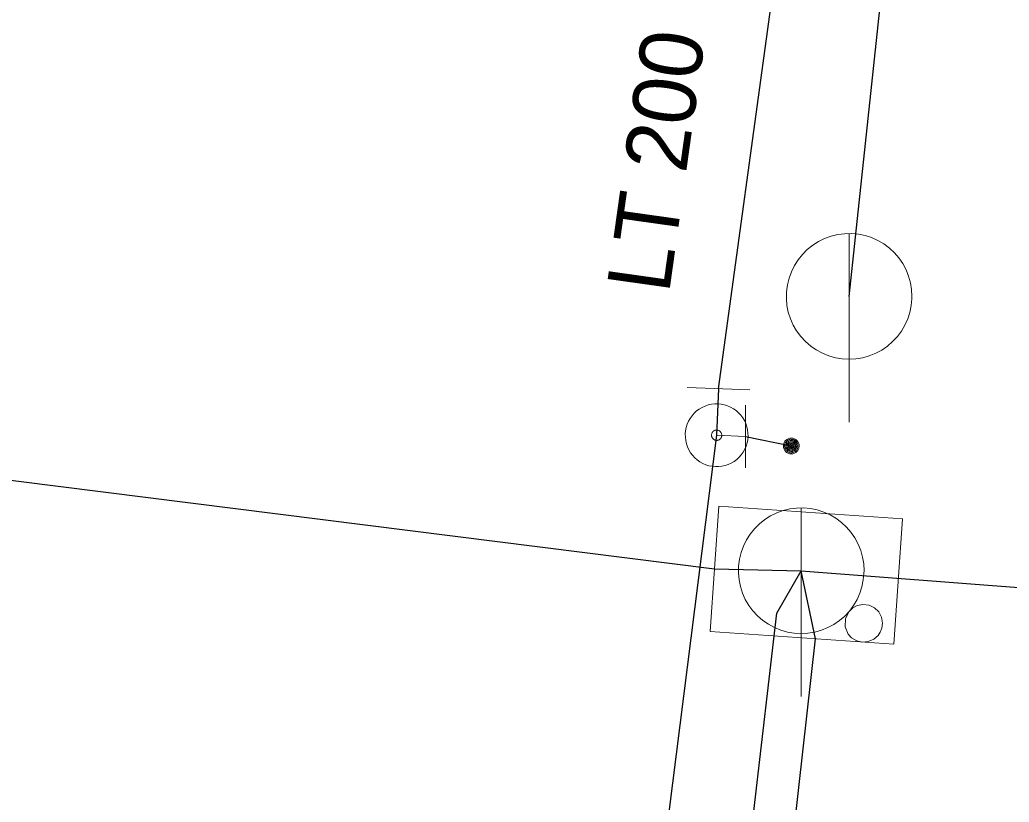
# Model space of a CAD drawing. Extents: x -783064 to -782702, y -1007904 to -1007145.
# Drawn here: x -782795.29 to -782779.54, y -1007420.35 to -1007407.9 of the extents above; entities that cross this region are included whole.
import ezdxf

# ---------------------------------------------------------------- set-up
doc = ezdxf.new("R2010")
doc.units = 0
doc.header["$LTSCALE"] = 0.4
for name, color, linetype, lineweight in [('1', 7, 'Continuous', 13), ('14', 7, 'Continuous', 13), ('17', 7, 'Continuous', 25), ('22', 7, 'Continuous', 13), ('34', 7, 'Continuous', 13), ('47', 7, 'Continuous', 13), ('9', 7, 'Continuous', 13)]:
    doc.layers.add(name, color=color, linetype=linetype, lineweight=lineweight)

msp = doc.modelspace()

# ---------------------------------------------------------------- linework, layer by layer
at = {"layer": '1'}
for points in [[(-782784.165, -1007415.638), (-782781.242, -1007415.839), (-782781.38, -1007417.835), (-782784.303, -1007417.633)], [(-782782.105, -1007417.672), (-782782.153, -1007417.558), (-782782.149, -1007417.428), (-782782.097, -1007417.32), (-782782.032, -1007417.256), (-782781.962, -1007417.219), (-782781.87, -1007417.201), (-782781.773, -1007417.213), (-782781.686, -1007417.255), (-782781.619, -1007417.32), (-782781.574, -1007417.403), (-782781.558, -1007417.501), (-782781.569, -1007417.581), (-782781.594, -1007417.643), (-782781.628, -1007417.694), (-782781.698, -1007417.755), (-782781.788, -1007417.793), (-782781.878, -1007417.8), (-782781.969, -1007417.78), (-782782.05, -1007417.732)]]:
    msp.add_lwpolyline(points, close=True, dxfattribs=at)
at = {"layer": '14'}
msp.add_line((-782784.199, -1007414.51), (-782783.739, -1007414.53), dxfattribs=at)
at = {"layer": '14', "lineweight": 25}
msp.add_line((-782782.853, -1007416.665), (-782749.03, -1007419.27), dxfattribs=at)
for points in [[(-782782.09, -1007412.3), (-782779.714, -1007390.038), (-782779.371, -1007386.822), (-782778.267, -1007376.47), (-782778.092, -1007374.836), (-782777.771, -1007371.826), (-782777.162, -1007366.117), (-782777.052, -1007365.088), (-782776.611, -1007360.948), (-782776.357, -1007358.573), (-782775.227, -1007347.977), (-782775.18, -1007347.535), (-782774.984, -1007345.702), (-782774.133, -1007337.723)], [(-782816.93, -1007412.519), (-782784.234, -1007416.636), (-782782.853, -1007416.665)], [(-782789.989, -1007474.3), (-782789.55, -1007470.605), (-782788.26, -1007459.742), (-782786.499, -1007444.926), (-782784.094, -1007424.689), (-782783.243, -1007417.342), (-782782.853, -1007416.665)], [(-782789.92, -1007482.8), (-782782.627, -1007417.749), (-782782.853, -1007416.665)]]:
    msp.add_lwpolyline(points, dxfattribs=at)
at = {"layer": '17'}
for p, q in [((-782784.17, -1007413.77), (-782782.979, -1007405.1)), ((-782784.17, -1007413.77), (-782784.199, -1007414.51)), ((-782783.739, -1007414.53), (-782783.01, -1007414.68))]:
    msp.add_line(p, q, dxfattribs=at)
msp.add_lwpolyline([(-782784.199, -1007414.51), (-782788.17, -1007445.88), (-782789.899, -1007459.31), (-782791.09, -1007469.35), (-782793.219, -1007488.27), (-782794.285, -1007499.072), (-782794.78, -1007504.08), (-782795.89, -1007514.14), (-782797.23, -1007526.05), (-782799.52, -1007547.12), (-782801.219, -1007562.54)], dxfattribs=at)
at = {"layer": '22'}
for p, q in [((-782782.09, -1007414.3), (-782782.089, -1007411.3)), ((-782782.853, -1007418.665), (-782782.852, -1007415.665))]:
    msp.add_line(p, q, dxfattribs=at)
for points in [[(-782781.09, -1007412.3), (-782781.095, -1007412.191), (-782781.113, -1007412.083), (-782781.143, -1007411.977), (-782781.183, -1007411.876), (-782781.235, -1007411.779), (-782781.297, -1007411.689), (-782781.369, -1007411.606), (-782781.449, -1007411.532), (-782781.537, -1007411.466), (-782781.631, -1007411.411), (-782781.731, -1007411.366), (-782781.836, -1007411.333), (-782781.943, -1007411.311), (-782782.052, -1007411.301), (-782782.162, -1007411.303), (-782782.27, -1007411.317), (-782782.377, -1007411.342), (-782782.48, -1007411.379), (-782782.578, -1007411.428), (-782782.67, -1007411.486), (-782782.756, -1007411.555), (-782782.833, -1007411.632), (-782782.902, -1007411.718), (-782782.961, -1007411.81), (-782783.009, -1007411.908), (-782783.046, -1007412.011), (-782783.072, -1007412.118), (-782783.086, -1007412.226), (-782783.089, -1007412.336), (-782783.079, -1007412.445), (-782783.058, -1007412.552), (-782783.024, -1007412.656), (-782782.98, -1007412.756), (-782782.925, -1007412.851), (-782782.859, -1007412.939), (-782782.785, -1007413.019), (-782782.702, -1007413.091), (-782782.612, -1007413.153), (-782782.516, -1007413.205), (-782782.414, -1007413.246), (-782782.309, -1007413.276), (-782782.201, -1007413.294), (-782782.091, -1007413.3), (-782781.982, -1007413.294), (-782781.874, -1007413.276), (-782781.769, -1007413.247), (-782781.667, -1007413.206), (-782781.57, -1007413.154), (-782781.48, -1007413.092), (-782781.397, -1007413.021), (-782781.322, -1007412.941), (-782781.257, -1007412.853), (-782781.201, -1007412.759), (-782781.157, -1007412.659), (-782781.123, -1007412.555), (-782781.101, -1007412.447), (-782781.091, -1007412.338)], [(-782781.853, -1007416.665), (-782781.858, -1007416.556), (-782781.876, -1007416.448), (-782781.906, -1007416.342), (-782781.946, -1007416.241), (-782781.998, -1007416.144), (-782782.06, -1007416.054), (-782782.132, -1007415.971), (-782782.212, -1007415.897), (-782782.3, -1007415.831), (-782782.394, -1007415.776), (-782782.494, -1007415.731), (-782782.599, -1007415.698), (-782782.706, -1007415.676), (-782782.815, -1007415.666), (-782782.925, -1007415.668), (-782783.033, -1007415.682), (-782783.14, -1007415.707), (-782783.243, -1007415.744), (-782783.341, -1007415.793), (-782783.433, -1007415.851), (-782783.519, -1007415.92), (-782783.596, -1007415.997), (-782783.665, -1007416.083), (-782783.724, -1007416.175), (-782783.772, -1007416.273), (-782783.809, -1007416.376), (-782783.835, -1007416.483), (-782783.849, -1007416.591), (-782783.852, -1007416.701), (-782783.842, -1007416.81), (-782783.821, -1007416.917), (-782783.787, -1007417.021), (-782783.743, -1007417.121), (-782783.688, -1007417.216), (-782783.622, -1007417.304), (-782783.548, -1007417.384), (-782783.465, -1007417.456), (-782783.375, -1007417.518), (-782783.279, -1007417.57), (-782783.177, -1007417.611), (-782783.072, -1007417.641), (-782782.964, -1007417.659), (-782782.854, -1007417.665), (-782782.745, -1007417.659), (-782782.637, -1007417.641), (-782782.532, -1007417.612), (-782782.43, -1007417.571), (-782782.333, -1007417.519), (-782782.243, -1007417.457), (-782782.16, -1007417.386), (-782782.085, -1007417.306), (-782782.02, -1007417.218), (-782781.964, -1007417.124), (-782781.92, -1007417.024), (-782781.886, -1007416.92), (-782781.864, -1007416.812), (-782781.854, -1007416.703)]]:
    msp.add_lwpolyline(points, close=True, dxfattribs=at)
at = {"layer": '34'}
for p, q in [((-782783.67, -1007413.789), (-782784.669, -1007413.749)), ((-782783.739, -1007414.03), (-782783.739, -1007415.03))]:
    msp.add_line(p, q, dxfattribs=at)
at = {"layer": '47'}
for points in [[(-782784.219, -1007415.009), (-782784.167, -1007415.008), (-782784.114, -1007415.002), (-782784.064, -1007414.99), (-782784.014, -1007414.974), (-782783.966, -1007414.952), (-782783.921, -1007414.925), (-782783.88, -1007414.894), (-782783.841, -1007414.858), (-782783.807, -1007414.82), (-782783.776, -1007414.777), (-782783.75, -1007414.731), (-782783.73, -1007414.683), (-782783.714, -1007414.633), (-782783.704, -1007414.582), (-782783.699, -1007414.53), (-782783.7, -1007414.478), (-782783.706, -1007414.425), (-782783.718, -1007414.374), (-782783.734, -1007414.325), (-782783.756, -1007414.277), (-782783.783, -1007414.232), (-782783.814, -1007414.19), (-782783.85, -1007414.151), (-782783.888, -1007414.117), (-782783.931, -1007414.087), (-782783.977, -1007414.061), (-782784.025, -1007414.04), (-782784.075, -1007414.025), (-782784.126, -1007414.015), (-782784.178, -1007414.01), (-782784.23, -1007414.011), (-782784.283, -1007414.017), (-782784.334, -1007414.028), (-782784.383, -1007414.045), (-782784.431, -1007414.067), (-782784.476, -1007414.093), (-782784.518, -1007414.124), (-782784.557, -1007414.16), (-782784.591, -1007414.199), (-782784.621, -1007414.242), (-782784.647, -1007414.288), (-782784.668, -1007414.335), (-782784.683, -1007414.386), (-782784.693, -1007414.437), (-782784.698, -1007414.489), (-782784.697, -1007414.541), (-782784.691, -1007414.594), (-782784.68, -1007414.644), (-782784.663, -1007414.694), (-782784.641, -1007414.742), (-782784.615, -1007414.787), (-782784.584, -1007414.828), (-782784.548, -1007414.867), (-782784.509, -1007414.901), (-782784.466, -1007414.932), (-782784.42, -1007414.958), (-782784.373, -1007414.978), (-782784.322, -1007414.994), (-782784.271, -1007415.004)], [(-782784.202, -1007414.591), (-782784.193, -1007414.592), (-782784.185, -1007414.59), (-782784.177, -1007414.588), (-782784.169, -1007414.586), (-782784.16, -1007414.582), (-782784.153, -1007414.577), (-782784.146, -1007414.573), (-782784.14, -1007414.567), (-782784.134, -1007414.56), (-782784.129, -1007414.553), (-782784.125, -1007414.546), (-782784.122, -1007414.538), (-782784.119, -1007414.53), (-782784.117, -1007414.522), (-782784.117, -1007414.513), (-782784.116, -1007414.504), (-782784.118, -1007414.496), (-782784.12, -1007414.488), (-782784.122, -1007414.48), (-782784.126, -1007414.471), (-782784.131, -1007414.464), (-782784.135, -1007414.457), (-782784.141, -1007414.451), (-782784.148, -1007414.444), (-782784.155, -1007414.44), (-782784.162, -1007414.436), (-782784.17, -1007414.433), (-782784.178, -1007414.43), (-782784.186, -1007414.428), (-782784.195, -1007414.428), (-782784.204, -1007414.427), (-782784.212, -1007414.429), (-782784.22, -1007414.431), (-782784.228, -1007414.433), (-782784.237, -1007414.437), (-782784.244, -1007414.441), (-782784.251, -1007414.446), (-782784.257, -1007414.452), (-782784.264, -1007414.459), (-782784.268, -1007414.466), (-782784.272, -1007414.473), (-782784.275, -1007414.481), (-782784.278, -1007414.489), (-782784.28, -1007414.497), (-782784.28, -1007414.506), (-782784.281, -1007414.515), (-782784.279, -1007414.523), (-782784.277, -1007414.531), (-782784.275, -1007414.539), (-782784.271, -1007414.548), (-782784.267, -1007414.555), (-782784.262, -1007414.562), (-782784.256, -1007414.568), (-782784.249, -1007414.574), (-782784.242, -1007414.579), (-782784.235, -1007414.583), (-782784.227, -1007414.586), (-782784.219, -1007414.589), (-782784.211, -1007414.591)]]:
    msp.add_lwpolyline(points, close=True, dxfattribs=at)
at = {"layer": '9'}
for points in [[(-782783.136, -1007414.68), (-782783.136, -1007414.693), (-782783.134, -1007414.706), (-782783.131, -1007414.719), (-782783.126, -1007414.731), (-782783.12, -1007414.743), (-782783.113, -1007414.754), (-782783.105, -1007414.764), (-782783.095, -1007414.774), (-782783.085, -1007414.782), (-782783.074, -1007414.789), (-782783.062, -1007414.795), (-782783.05, -1007414.8), (-782783.037, -1007414.803), (-782783.024, -1007414.805), (-782783.011, -1007414.807), (-782782.998, -1007414.806), (-782782.985, -1007414.804), (-782782.972, -1007414.801), (-782782.96, -1007414.796), (-782782.948, -1007414.79), (-782782.937, -1007414.783), (-782782.927, -1007414.775), (-782782.917, -1007414.765), (-782782.909, -1007414.755), (-782782.902, -1007414.744), (-782782.896, -1007414.732), (-782782.891, -1007414.72), (-782782.888, -1007414.707), (-782782.886, -1007414.694), (-782782.884, -1007414.681), (-782782.885, -1007414.668), (-782782.887, -1007414.655), (-782782.89, -1007414.642), (-782782.895, -1007414.63), (-782782.901, -1007414.618), (-782782.908, -1007414.607), (-782782.916, -1007414.597), (-782782.926, -1007414.587), (-782782.936, -1007414.579), (-782782.947, -1007414.572), (-782782.959, -1007414.566), (-782782.971, -1007414.561), (-782782.984, -1007414.558), (-782782.997, -1007414.556), (-782783.01, -1007414.555), (-782783.023, -1007414.555), (-782783.036, -1007414.557), (-782783.049, -1007414.56), (-782783.061, -1007414.565), (-782783.073, -1007414.571), (-782783.084, -1007414.578), (-782783.094, -1007414.586), (-782783.104, -1007414.596), (-782783.112, -1007414.606), (-782783.119, -1007414.617), (-782783.125, -1007414.629), (-782783.13, -1007414.641), (-782783.133, -1007414.654), (-782783.135, -1007414.667)], [(-782783.116, -1007414.68), (-782783.117, -1007414.691), (-782783.115, -1007414.702), (-782783.112, -1007414.713), (-782783.108, -1007414.723), (-782783.103, -1007414.733), (-782783.097, -1007414.742), (-782783.09, -1007414.751), (-782783.082, -1007414.759), (-782783.073, -1007414.766), (-782783.064, -1007414.772), (-782783.054, -1007414.777), (-782783.044, -1007414.781), (-782783.033, -1007414.784), (-782783.022, -1007414.787), (-782783.011, -1007414.787), (-782783, -1007414.787), (-782782.989, -1007414.785), (-782782.978, -1007414.782), (-782782.968, -1007414.778), (-782782.958, -1007414.773), (-782782.949, -1007414.767), (-782782.94, -1007414.76), (-782782.932, -1007414.752), (-782782.925, -1007414.743), (-782782.919, -1007414.734), (-782782.914, -1007414.724), (-782782.91, -1007414.714), (-782782.907, -1007414.703), (-782782.905, -1007414.692), (-782782.904, -1007414.681), (-782782.904, -1007414.67), (-782782.906, -1007414.659), (-782782.909, -1007414.648), (-782782.913, -1007414.638), (-782782.918, -1007414.628), (-782782.924, -1007414.619), (-782782.931, -1007414.61), (-782782.939, -1007414.602), (-782782.948, -1007414.595), (-782782.957, -1007414.589), (-782782.967, -1007414.584), (-782782.977, -1007414.58), (-782782.988, -1007414.577), (-782782.999, -1007414.575), (-782783.01, -1007414.575), (-782783.021, -1007414.574), (-782783.032, -1007414.576), (-782783.043, -1007414.579), (-782783.053, -1007414.583), (-782783.063, -1007414.588), (-782783.072, -1007414.594), (-782783.081, -1007414.601), (-782783.089, -1007414.609), (-782783.096, -1007414.618), (-782783.102, -1007414.627), (-782783.107, -1007414.637), (-782783.111, -1007414.647), (-782783.114, -1007414.658), (-782783.116, -1007414.669)], [(-782783.097, -1007414.68), (-782783.097, -1007414.689), (-782783.096, -1007414.698), (-782783.093, -1007414.707), (-782783.09, -1007414.715), (-782783.086, -1007414.723), (-782783.081, -1007414.731), (-782783.075, -1007414.738), (-782783.069, -1007414.744), (-782783.062, -1007414.75), (-782783.054, -1007414.755), (-782783.046, -1007414.759), (-782783.038, -1007414.762), (-782783.029, -1007414.765), (-782783.02, -1007414.766), (-782783.011, -1007414.768), (-782783.002, -1007414.767), (-782782.993, -1007414.766), (-782782.984, -1007414.763), (-782782.976, -1007414.76), (-782782.968, -1007414.756), (-782782.96, -1007414.751), (-782782.953, -1007414.745), (-782782.947, -1007414.739), (-782782.941, -1007414.732), (-782782.936, -1007414.724), (-782782.932, -1007414.716), (-782782.929, -1007414.708), (-782782.926, -1007414.699), (-782782.925, -1007414.69), (-782782.923, -1007414.681), (-782782.924, -1007414.672), (-782782.925, -1007414.663), (-782782.928, -1007414.654), (-782782.931, -1007414.646), (-782782.935, -1007414.638), (-782782.94, -1007414.63), (-782782.946, -1007414.623), (-782782.952, -1007414.617), (-782782.959, -1007414.611), (-782782.967, -1007414.606), (-782782.975, -1007414.602), (-782782.983, -1007414.599), (-782782.992, -1007414.596), (-782783.001, -1007414.595), (-782783.01, -1007414.594), (-782783.019, -1007414.594), (-782783.028, -1007414.595), (-782783.037, -1007414.598), (-782783.045, -1007414.601), (-782783.053, -1007414.605), (-782783.061, -1007414.61), (-782783.068, -1007414.616), (-782783.074, -1007414.622), (-782783.08, -1007414.629), (-782783.085, -1007414.637), (-782783.089, -1007414.645), (-782783.092, -1007414.653), (-782783.095, -1007414.662), (-782783.096, -1007414.671)], [(-782783.077, -1007414.68), (-782783.077, -1007414.687), (-782783.076, -1007414.694), (-782783.075, -1007414.701), (-782783.072, -1007414.707), (-782783.069, -1007414.713), (-782783.065, -1007414.719), (-782783.061, -1007414.725), (-782783.056, -1007414.73), (-782783.05, -1007414.734), (-782783.044, -1007414.738), (-782783.038, -1007414.741), (-782783.032, -1007414.744), (-782783.025, -1007414.745), (-782783.018, -1007414.748), (-782783.011, -1007414.748), (-782783.004, -1007414.748), (-782782.997, -1007414.746), (-782782.99, -1007414.745), (-782782.984, -1007414.742), (-782782.977, -1007414.739), (-782782.972, -1007414.735), (-782782.966, -1007414.731), (-782782.961, -1007414.726), (-782782.957, -1007414.72), (-782782.953, -1007414.714), (-782782.95, -1007414.708), (-782782.947, -1007414.702), (-782782.945, -1007414.695), (-782782.944, -1007414.688), (-782782.943, -1007414.681), (-782782.943, -1007414.674), (-782782.944, -1007414.667), (-782782.946, -1007414.66), (-782782.949, -1007414.654), (-782782.952, -1007414.647), (-782782.956, -1007414.642), (-782782.96, -1007414.636), (-782782.965, -1007414.631), (-782782.971, -1007414.627), (-782782.976, -1007414.623), (-782782.983, -1007414.62), (-782782.989, -1007414.617), (-782782.996, -1007414.615), (-782783.003, -1007414.614), (-782783.01, -1007414.614), (-782783.017, -1007414.614), (-782783.024, -1007414.614), (-782783.031, -1007414.616), (-782783.037, -1007414.619), (-782783.043, -1007414.622), (-782783.049, -1007414.626), (-782783.055, -1007414.63), (-782783.06, -1007414.635), (-782783.064, -1007414.641), (-782783.068, -1007414.646), (-782783.071, -1007414.653), (-782783.074, -1007414.659), (-782783.075, -1007414.666), (-782783.077, -1007414.673)], [(-782783.057, -1007414.68), (-782783.057, -1007414.685), (-782783.057, -1007414.69), (-782783.056, -1007414.695), (-782783.054, -1007414.699), (-782783.052, -1007414.704), (-782783.049, -1007414.708), (-782783.046, -1007414.711), (-782783.042, -1007414.715), (-782783.039, -1007414.718), (-782783.035, -1007414.721), (-782783.03, -1007414.723), (-782783.026, -1007414.725), (-782783.021, -1007414.726), (-782783.016, -1007414.728), (-782783.011, -1007414.728), (-782783.006, -1007414.728), (-782783.001, -1007414.727), (-782782.996, -1007414.726), (-782782.992, -1007414.724), (-782782.987, -1007414.722), (-782782.983, -1007414.719), (-782782.979, -1007414.716), (-782782.976, -1007414.712), (-782782.973, -1007414.709), (-782782.97, -1007414.705), (-782782.968, -1007414.7), (-782782.966, -1007414.696), (-782782.965, -1007414.691), (-782782.964, -1007414.686), (-782782.963, -1007414.681), (-782782.963, -1007414.676), (-782782.964, -1007414.671), (-782782.965, -1007414.666), (-782782.967, -1007414.662), (-782782.969, -1007414.657), (-782782.972, -1007414.653), (-782782.975, -1007414.649), (-782782.978, -1007414.646), (-782782.982, -1007414.643), (-782782.986, -1007414.64), (-782782.991, -1007414.638), (-782782.995, -1007414.636), (-782783, -1007414.635), (-782783.005, -1007414.634), (-782783.01, -1007414.634), (-782783.015, -1007414.634), (-782783.02, -1007414.635), (-782783.025, -1007414.635), (-782783.029, -1007414.637), (-782783.034, -1007414.639), (-782783.038, -1007414.642), (-782783.041, -1007414.645), (-782783.045, -1007414.648), (-782783.048, -1007414.652), (-782783.051, -1007414.656), (-782783.053, -1007414.661), (-782783.055, -1007414.665), (-782783.056, -1007414.67), (-782783.057, -1007414.675)], [(-782783.037, -1007414.68), (-782783.037, -1007414.683), (-782783.038, -1007414.686), (-782783.037, -1007414.688), (-782783.036, -1007414.691), (-782783.035, -1007414.694), (-782783.033, -1007414.696), (-782783.031, -1007414.698), (-782783.029, -1007414.7), (-782783.027, -1007414.702), (-782783.025, -1007414.704), (-782783.022, -1007414.706), (-782783.019, -1007414.707), (-782783.017, -1007414.707), (-782783.014, -1007414.708), (-782783.011, -1007414.708), (-782783.008, -1007414.708), (-782783.005, -1007414.708), (-782783.002, -1007414.707), (-782783, -1007414.706), (-782782.997, -1007414.705), (-782782.995, -1007414.703), (-782782.992, -1007414.701), (-782782.99, -1007414.699), (-782782.989, -1007414.697), (-782782.987, -1007414.695), (-782782.986, -1007414.692), (-782782.984, -1007414.689), (-782782.984, -1007414.687), (-782782.983, -1007414.684), (-782782.982, -1007414.681), (-782782.983, -1007414.678), (-782782.983, -1007414.675), (-782782.984, -1007414.672), (-782782.985, -1007414.67), (-782782.986, -1007414.667), (-782782.988, -1007414.665), (-782782.989, -1007414.662), (-782782.991, -1007414.66), (-782782.994, -1007414.659), (-782782.996, -1007414.657), (-782782.999, -1007414.656), (-782783.001, -1007414.655), (-782783.004, -1007414.654), (-782783.007, -1007414.654), (-782783.01, -1007414.653), (-782783.013, -1007414.654), (-782783.016, -1007414.653), (-782783.018, -1007414.655), (-782783.021, -1007414.655), (-782783.024, -1007414.656), (-782783.026, -1007414.658), (-782783.028, -1007414.659), (-782783.03, -1007414.661), (-782783.032, -1007414.664), (-782783.034, -1007414.666), (-782783.035, -1007414.669), (-782783.036, -1007414.671), (-782783.037, -1007414.674), (-782783.037, -1007414.677)], [(-782783.018, -1007414.68), (-782783.018, -1007414.682), (-782783.018, -1007414.682), (-782783.017, -1007414.682), (-782783.017, -1007414.684), (-782783.018, -1007414.685), (-782783.016, -1007414.685), (-782783.016, -1007414.685), (-782783.016, -1007414.687), (-782783.016, -1007414.687), (-782783.015, -1007414.688), (-782783.013, -1007414.688), (-782783.013, -1007414.688), (-782783.013, -1007414.689), (-782783.011, -1007414.689), (-782783.011, -1007414.689), (-782783.01, -1007414.689), (-782783.009, -1007414.689), (-782783.009, -1007414.688), (-782783.008, -1007414.688), (-782783.006, -1007414.688), (-782783.006, -1007414.687), (-782783.006, -1007414.687), (-782783.005, -1007414.686), (-782783.005, -1007414.686), (-782783.003, -1007414.685), (-782783.003, -1007414.684), (-782783.002, -1007414.683), (-782783.002, -1007414.683), (-782783.002, -1007414.682), (-782783.002, -1007414.681), (-782783.002, -1007414.68), (-782783.002, -1007414.679), (-782783.002, -1007414.679), (-782783.003, -1007414.678), (-782783.003, -1007414.677), (-782783.004, -1007414.676), (-782783.004, -1007414.676), (-782783.005, -1007414.675), (-782783.005, -1007414.675), (-782783.006, -1007414.674), (-782783.007, -1007414.674), (-782783.008, -1007414.673), (-782783.008, -1007414.673), (-782783.009, -1007414.673), (-782783.01, -1007414.673), (-782783.011, -1007414.673), (-782783.012, -1007414.673), (-782783.012, -1007414.673), (-782783.013, -1007414.674), (-782783.014, -1007414.673), (-782783.015, -1007414.675), (-782783.015, -1007414.675), (-782783.016, -1007414.675), (-782783.016, -1007414.675), (-782783.017, -1007414.677), (-782783.017, -1007414.678), (-782783.017, -1007414.679), (-782783.018, -1007414.679), (-782783.018, -1007414.68)]]:
    msp.add_lwpolyline(points, close=True, dxfattribs=at)

# ---------------------------------------------------------------- texts
at = {"layer": '1'}
msp.add_text('LT 200', height=1, rotation=82, dxfattribs=at).set_placement((-782784.958, -1007412.272))

doc.saveas('drawing.dxf')
